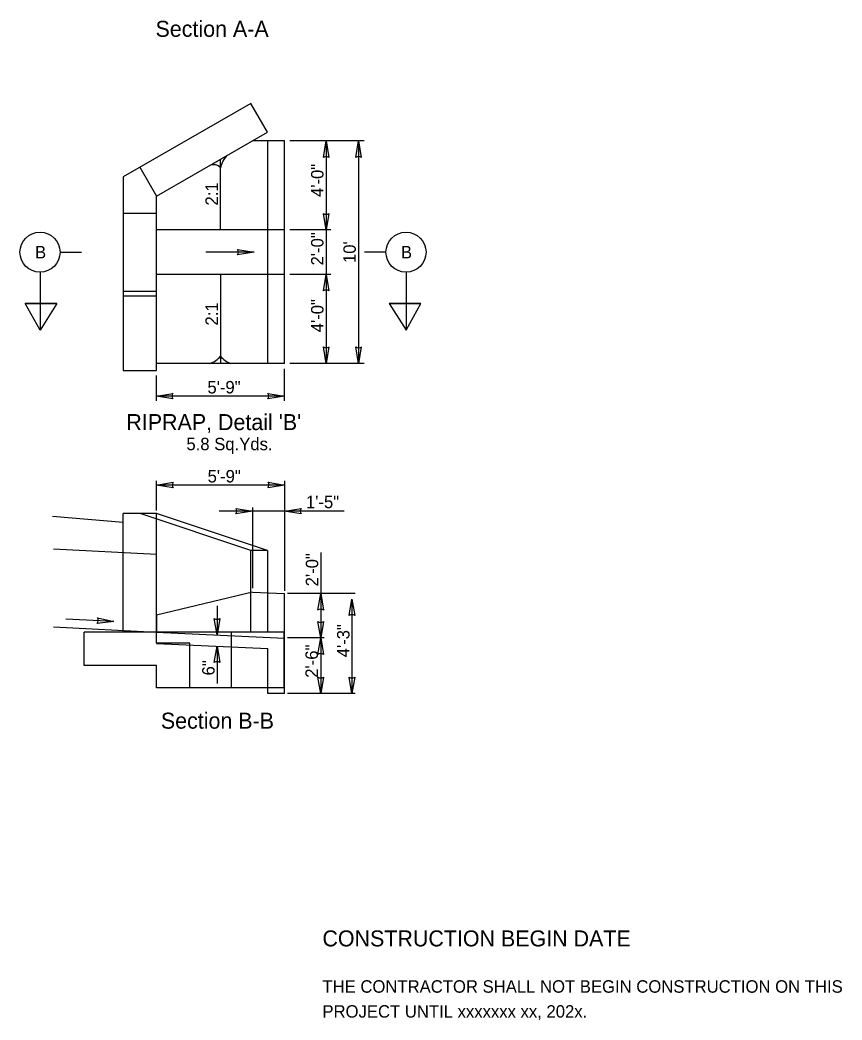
# Model space of a CAD drawing. Extents: x -30 to 76, y -31 to 50.
# Drawn here: x -17.76 to -8.53, y 27.07 to 38.31 of the extents above; entities that cross this region are included whole.
import ezdxf

# ---------------------------------------------------------------- set-up
doc = ezdxf.new("R2010")
doc.units = 0
for name, color, linetype in [('BR_P_Gen_Text', 7, 'Continuous'), ('Default', 7, 'Continuous'), ('DR_Gutter', 7, 'Continuous'), ('DR_P_Culvert', 7, 'Continuous'), ('DR_P_Headwall', 7, 'Continuous'), ('DT_P_Slope_Break_Line', 7, 'Continuous'), ('GK_Drainage_Nodes', 7, 'Continuous'), ('SH_Data', 7, 'Continuous'), ('SH_Text', 7, 'Continuous'), ('TX_X_1', 7, 'Continuous'), ('XS_P_Finished_Grade', 7, 'Continuous')]:
    doc.layers.add(name, color=color, linetype=linetype)

msp = doc.modelspace()

# ---------------------------------------------------------------- linework, layer by layer
at = {"layer": 'BR_P_Gen_Text'}
for p, q in [((-17.311, 35.698), (-17.069, 35.698)), ((-13.649, 35.698), (-13.892, 35.698)), ((-17.536, 35.473), (-17.536, 34.822)), ((-13.424, 35.473), (-13.424, 34.822)), ((-17.702, 35.122), (-17.348, 35.122)), ((-17.536, 34.822), (-17.702, 35.122)), ((-17.702, 35.122), (-17.348, 35.122)), ((-17.348, 35.122), (-17.702, 35.122)), ((-17.702, 35.122), (-17.348, 35.122)), ((-17.536, 34.822), (-17.702, 35.122)), ((-17.348, 35.122), (-17.536, 34.822)), ((-17.348, 35.122), (-17.536, 34.822)), ((-13.258, 35.122), (-13.613, 35.122)), ((-13.613, 35.122), (-13.424, 34.822)), ((-13.258, 35.122), (-13.613, 35.122)), ((-13.613, 35.122), (-13.258, 35.122)), ((-13.258, 35.122), (-13.613, 35.122)), ((-13.613, 35.122), (-13.424, 34.822)), ((-13.424, 34.822), (-13.258, 35.122)), ((-13.424, 34.822), (-13.258, 35.122))]:
    msp.add_line(p, q, dxfattribs=at)
for centre in [(-17.536, 35.698), (-13.424, 35.698)]:
    msp.add_circle(centre, 0.225, dxfattribs=at)
at = {"layer": 'Default'}
for p, q in [((-14.352, 36.763), (-14.321, 36.948)), ((-14.321, 36.948), (-14.29, 36.762)), ((-13.987, 36.763), (-13.957, 36.948)), ((-13.957, 36.948), (-13.926, 36.762)), ((-14.352, 36.763), (-14.352, 36.763)), ((-14.29, 36.762), (-14.29, 36.763)), ((-13.987, 36.763), (-13.987, 36.763)), ((-13.926, 36.762), (-13.926, 36.763)), ((-14.321, 35.948), (-14.352, 36.133)), ((-14.352, 36.133), (-14.352, 36.133)), ((-14.29, 36.133), (-14.321, 35.948)), ((-14.29, 36.133), (-14.29, 36.133)), ((-15.316, 35.729), (-15.316, 35.729)), ((-15.316, 35.729), (-15.131, 35.698)), ((-15.131, 35.698), (-15.317, 35.667)), ((-15.317, 35.667), (-15.317, 35.667)), ((-14.352, 35.263), (-14.321, 35.448)), ((-14.321, 35.448), (-14.29, 35.262)), ((-14.352, 35.263), (-14.352, 35.263)), ((-14.29, 35.262), (-14.29, 35.263)), ((-14.321, 34.448), (-14.352, 34.633)), ((-14.352, 34.633), (-14.352, 34.633)), ((-14.29, 34.633), (-14.321, 34.448)), ((-14.29, 34.633), (-14.29, 34.633)), ((-13.957, 34.448), (-13.987, 34.633)), ((-13.987, 34.633), (-13.987, 34.633)), ((-13.926, 34.633), (-13.957, 34.448)), ((-13.926, 34.633), (-13.926, 34.633)), ((-16.229, 34.081), (-16.044, 34.112)), ((-16.044, 34.051), (-16.229, 34.081)), ((-16.044, 34.112), (-16.044, 34.112)), ((-16.044, 34.051), (-16.044, 34.051)), ((-14.975, 34.112), (-14.975, 34.112)), ((-14.975, 34.112), (-14.79, 34.081)), ((-14.79, 34.081), (-14.975, 34.051)), ((-14.975, 34.051), (-14.975, 34.051)), ((-16.226, 33.082), (-16.041, 33.113)), ((-16.041, 33.051), (-16.226, 33.082)), ((-16.041, 33.113), (-16.041, 33.113)), ((-16.041, 33.051), (-16.041, 33.051)), ((-14.789, 33.082), (-14.974, 33.051)), ((-14.974, 33.051), (-14.974, 33.051)), ((-14.973, 33.113), (-14.973, 33.113)), ((-14.973, 33.113), (-14.789, 33.082)), ((-15.334, 32.82), (-15.334, 32.82)), ((-15.334, 32.82), (-15.149, 32.789)), ((-14.789, 32.789), (-14.603, 32.82)), ((-14.603, 32.82), (-14.603, 32.82)), ((-15.149, 32.789), (-15.335, 32.758)), ((-15.335, 32.758), (-15.335, 32.758)), ((-14.604, 32.758), (-14.789, 32.789)), ((-14.604, 32.758), (-14.604, 32.758)), ((-14.413, 31.678), (-14.382, 31.863)), ((-14.382, 31.863), (-14.351, 31.678)), ((-14.062, 31.616), (-14.031, 31.801)), ((-14.031, 31.801), (-14, 31.615)), ((-16.89, 31.589), (-16.89, 31.589)), ((-16.89, 31.589), (-16.708, 31.548)), ((-15.547, 31.398), (-15.578, 31.583)), ((-15.578, 31.583), (-15.578, 31.583)), ((-15.516, 31.583), (-15.547, 31.398)), ((-15.516, 31.583), (-15.516, 31.583)), ((-14.413, 31.678), (-14.413, 31.678)), ((-14.351, 31.678), (-14.351, 31.678)), ((-14.062, 31.616), (-14.062, 31.616)), ((-14, 31.615), (-14, 31.615)), ((-16.708, 31.548), (-16.894, 31.527)), ((-16.894, 31.527), (-16.894, 31.527)), ((-14.382, 31.364), (-14.413, 31.55)), ((-14.413, 31.55), (-14.413, 31.55)), ((-14.351, 31.549), (-14.382, 31.364)), ((-14.351, 31.549), (-14.351, 31.549)), ((-14.413, 31.179), (-14.382, 31.364)), ((-14.382, 31.364), (-14.351, 31.179)), ((-15.578, 31.088), (-15.547, 31.273)), ((-15.547, 31.273), (-15.516, 31.087)), ((-14.413, 31.179), (-14.413, 31.179)), ((-14.351, 31.179), (-14.351, 31.179)), ((-15.578, 31.088), (-15.578, 31.088)), ((-15.516, 31.087), (-15.516, 31.087)), ((-14.382, 30.739), (-14.413, 30.925)), ((-14.413, 30.925), (-14.413, 30.925)), ((-14.351, 30.924), (-14.382, 30.739)), ((-14.351, 30.924), (-14.351, 30.924)), ((-14.031, 30.739), (-14.062, 30.925)), ((-14.062, 30.925), (-14.062, 30.925)), ((-14, 30.924), (-14.031, 30.739)), ((-14, 30.924), (-14, 30.924))]:
    msp.add_line(p, q, dxfattribs=at)
for centre, start, end in [((-14.321, 36.716), 56.178, 122.8588), ((-13.957, 36.716), 56.178, 122.8588), ((-14.32, 36.18), 236.178, 302.8588), ((-15.363, 35.698), 326.178, 32.8588), ((-14.321, 35.216), 56.178, 122.8588), ((-14.32, 34.68), 236.178, 302.8588), ((-13.956, 34.68), 236.178, 302.8588), ((-15.997, 34.081), 146.178, 212.8588), ((-15.022, 34.082), 326.178, 32.8588), ((-15.994, 33.081), 146.178, 212.8588), ((-15.021, 33.082), 326.178, 32.8588), ((-15.381, 32.789), 326.178, 32.8588), ((-14.556, 32.788), 146.178, 212.8588), ((-14.383, 31.631), 56.178, 122.8588), ((-16.939, 31.561), 323.0985, 29.7792), ((-15.547, 31.63), 236.178, 302.8588), ((-14.031, 31.569), 56.178, 122.8588), ((-14.382, 31.596), 236.178, 302.8588), ((-14.383, 31.132), 56.178, 122.8588), ((-15.548, 31.041), 56.178, 122.8588), ((-14.382, 30.971), 236.178, 302.8588), ((-14.03, 30.971), 236.178, 302.8588)]:
    msp.add_arc(centre, 0.0563, start, end, dxfattribs=at)
at = {"layer": 'DR_Gutter'}
for p, q in [((-14.79, 36.948), (-15.149, 36.948)), ((-14.977, 34.448), (-14.977, 36.948)), ((-14.79, 34.448), (-14.79, 36.948)), ((-14.79, 35.948), (-16.227, 35.948)), ((-14.79, 35.448), (-16.227, 35.448)), ((-14.79, 34.448), (-16.227, 34.448)), ((-15.149, 31.88), (-16.226, 31.619)), ((-15.149, 31.88), (-14.789, 31.863)), ((-14.789, 31.363), (-14.789, 31.863)), ((-16.226, 31.619), (-16.226, 31.429)), ((-16.226, 31.429), (-14.789, 31.363)), ((-16.226, 31.304), (-16.226, 31.429)), ((-14.789, 30.739), (-14.789, 31.363)), ((-16.226, 31.303), (-14.976, 31.247)), ((-14.976, 30.739), (-14.976, 31.247)), ((-14.789, 30.739), (-14.976, 30.739))]:
    msp.add_line(p, q, dxfattribs=at)
at = {"layer": 'DR_P_Culvert'}
for p, q in [((-16.601, 36.135), (-16.227, 36.135)), ((-16.228, 35.26), (-16.228, 36.135)), ((-16.601, 35.26), (-16.227, 35.26)), ((-17.383, 32.367), (-16.226, 32.305)), ((-16.226, 31.429), (-16.226, 32.305)), ((-17.383, 31.491), (-16.226, 31.429))]:
    msp.add_line(p, q, dxfattribs=at)
at = {"layer": 'DR_P_Headwall'}
for p, q in [((-16.413, 36.653), (-16.226, 36.328)), ((-16.228, 35.203), (-16.603, 35.204)), ((-16.226, 32.762), (-16.601, 32.762)), ((-16.601, 32.325), (-16.601, 32.762)), ((-15.166, 32.345), (-16.412, 32.762)), ((-16.226, 32.305), (-16.226, 32.762)), ((-14.98, 32.345), (-16.226, 32.762)), ((-16.601, 31.449), (-16.601, 32.325)), ((-14.98, 32.345), (-15.166, 32.345)), ((-15.166, 31.429), (-15.166, 32.345)), ((-14.98, 32.345), (-14.98, 31.872)), ((-14.98, 31.872), (-14.98, 31.429)), ((-17.039, 31.054), (-17.039, 31.429)), ((-16.226, 31.429), (-17.039, 31.429)), ((-16.601, 31.429), (-16.601, 31.449)), ((-16.226, 31.304), (-16.226, 31.429)), ((-14.793, 31.429), (-16.226, 31.429)), ((-15.386, 30.804), (-15.386, 31.429)), ((-14.793, 30.804), (-14.793, 31.429)), ((-15.851, 31.304), (-16.226, 31.304)), ((-15.851, 30.804), (-15.851, 31.304)), ((-16.226, 31.054), (-17.039, 31.054)), ((-16.226, 30.804), (-16.226, 31.054)), ((-15.851, 30.804), (-16.226, 30.804)), ((-14.976, 30.804), (-15.851, 30.804)), ((-14.793, 30.804), (-14.976, 30.804))]:
    msp.add_line(p, q, dxfattribs=at)
msp.add_lwpolyline([(-16.601, 34.37), (-16.229, 34.37), (-16.226, 36.328), (-14.98, 37.045), (-15.166, 37.367), (-16.601, 36.545)], close=True, dxfattribs=at)
at = {"layer": 'DT_P_Slope_Break_Line'}
for p, q in [((-15.629, 36.672), (-15.435, 36.784)), ((-15.508, 35.948), (-15.508, 36.741)), ((-15.508, 35.448), (-15.508, 34.448)), ((-15.391, 34.448), (-15.626, 34.448))]:
    msp.add_line(p, q, dxfattribs=at)
for centre, radius, start, end in [((-15.238, 36.589), 0.277, 135.4238, 168.0133), ((-15.587, 36.574), 0.107, 43.1008, 113.2446), ((-15.721, 34.708), 0.277, 290.0047, 320.0764), ((-15.296, 34.708), 0.277, 219.9236, 249.9953)]:
    msp.add_arc(centre, radius, start, end, dxfattribs=at)
at = {"layer": 'GK_Drainage_Nodes'}
for p, q in [((-16.599, 35.698), (-16.599, 35.698)), ((-16.224, 35.698), (-16.224, 35.698)), ((-16.224, 35.698), (-16.224, 35.698)), ((-16.224, 35.698), (-16.224, 35.698)), ((-16.224, 35.698), (-16.224, 35.698)), ((-16.224, 35.698), (-16.224, 35.698))]:
    msp.add_line(p, q, dxfattribs=at)
at = {"layer": 'SH_Data'}
for p, q in [((-13.894, 36.948), (-14.731, 36.948)), ((-14.321, 36.948), (-14.321, 35.948)), ((-13.957, 36.948), (-13.957, 34.448)), ((-14.27, 35.948), (-14.731, 35.948)), ((-14.321, 35.948), (-14.321, 35.448)), ((-15.131, 35.698), (-15.672, 35.698)), ((-14.27, 35.448), (-14.731, 35.448)), ((-14.321, 35.448), (-14.321, 34.448)), ((-14.79, 34.029), (-14.79, 34.389)), ((-13.894, 34.448), (-14.731, 34.448)), ((-16.229, 34.029), (-16.229, 34.314)), ((-14.79, 34.081), (-16.229, 34.081)), ((-16.226, 32.796), (-16.226, 33.13)), ((-14.789, 33.082), (-16.226, 33.082)), ((-14.789, 33.13), (-14.789, 31.895)), ((-15.149, 32.828), (-15.149, 31.922)), ((-15.149, 32.789), (-15.525, 32.789)), ((-14.789, 32.789), (-15.149, 32.789)), ((-14.12, 32.789), (-14.789, 32.789)), ((-14.382, 32.324), (-14.382, 31.863)), ((-13.996, 31.863), (-14.755, 31.863)), ((-14.382, 31.863), (-14.382, 31.364)), ((-14.031, 31.801), (-14.031, 30.739)), ((-15.547, 31.724), (-15.547, 31.398)), ((-16.708, 31.548), (-17.247, 31.577)), ((-14.345, 31.364), (-14.755, 31.364)), ((-14.382, 31.364), (-14.382, 30.739)), ((-15.547, 31.273), (-15.547, 30.853)), ((-13.996, 30.739), (-14.755, 30.739))]:
    msp.add_line(p, q, dxfattribs=at)
at = {"layer": 'XS_P_Finished_Grade'}
msp.add_line((-16.601, 32.662), (-17.394, 32.728), dxfattribs=at)

# ---------------------------------------------------------------- texts
at = {"layer": 'BR_P_Gen_Text'}
for p in [(-17.592, 35.628), (-13.481, 35.628)]:
    msp.add_text('B', height=0.14, dxfattribs=at).set_placement(p)
at = {"layer": 'SH_Text'}
for s, height, p in [('Section A-A', 0.18, (-16.238, 38.117)), ("RIPRAP, Detail 'B'", 0.18, (-16.566, 33.699)), ('Section B-B', 0.18, (-16.178, 30.345)), ('CONSTRUCTION BEGIN DATE', 0.18, (-14.363, 27.899)), ('THE CONTRACTOR SHALL NOT BEGIN CONSTRUCTION ON THIS', 0.14, (-14.363, 27.379)), ('PROJECT UNTIL xxxxxxx xx, 202x.', 0.14, (-14.363, 27.099))]:
    msp.add_text(s, height=height, dxfattribs=at).set_placement(p)
at = {"layer": 'TX_X_1'}
for s, p in [('4\'-0"', (-14.351, 36.318)), ('2:1', (-15.537, 36.222)), ('2\'-0"', (-14.351, 35.549)), ("10'", (-13.988, 35.576)), ('4\'-0"', (-14.351, 34.798)), ('2:1', (-15.537, 34.874)), ('2\'-0"', (-14.41, 31.944)), ('4\'-3"', (-14.059, 31.147)), ('2\'-6"', (-14.414, 30.917)), ('6"', (-15.574, 30.943))]:
    msp.add_text(s, height=0.14, rotation=90, dxfattribs=at).set_placement(p)
for s, p in [('5\'-9"', (-15.655, 34.111)), ('5.8 Sq.Yds.', (-15.891, 33.473)), ('5\'-9"', (-15.653, 33.111)), ('1\'-5"', (-14.548, 32.822))]:
    msp.add_text(s, height=0.14, dxfattribs=at).set_placement(p)

doc.saveas('drawing.dxf')
